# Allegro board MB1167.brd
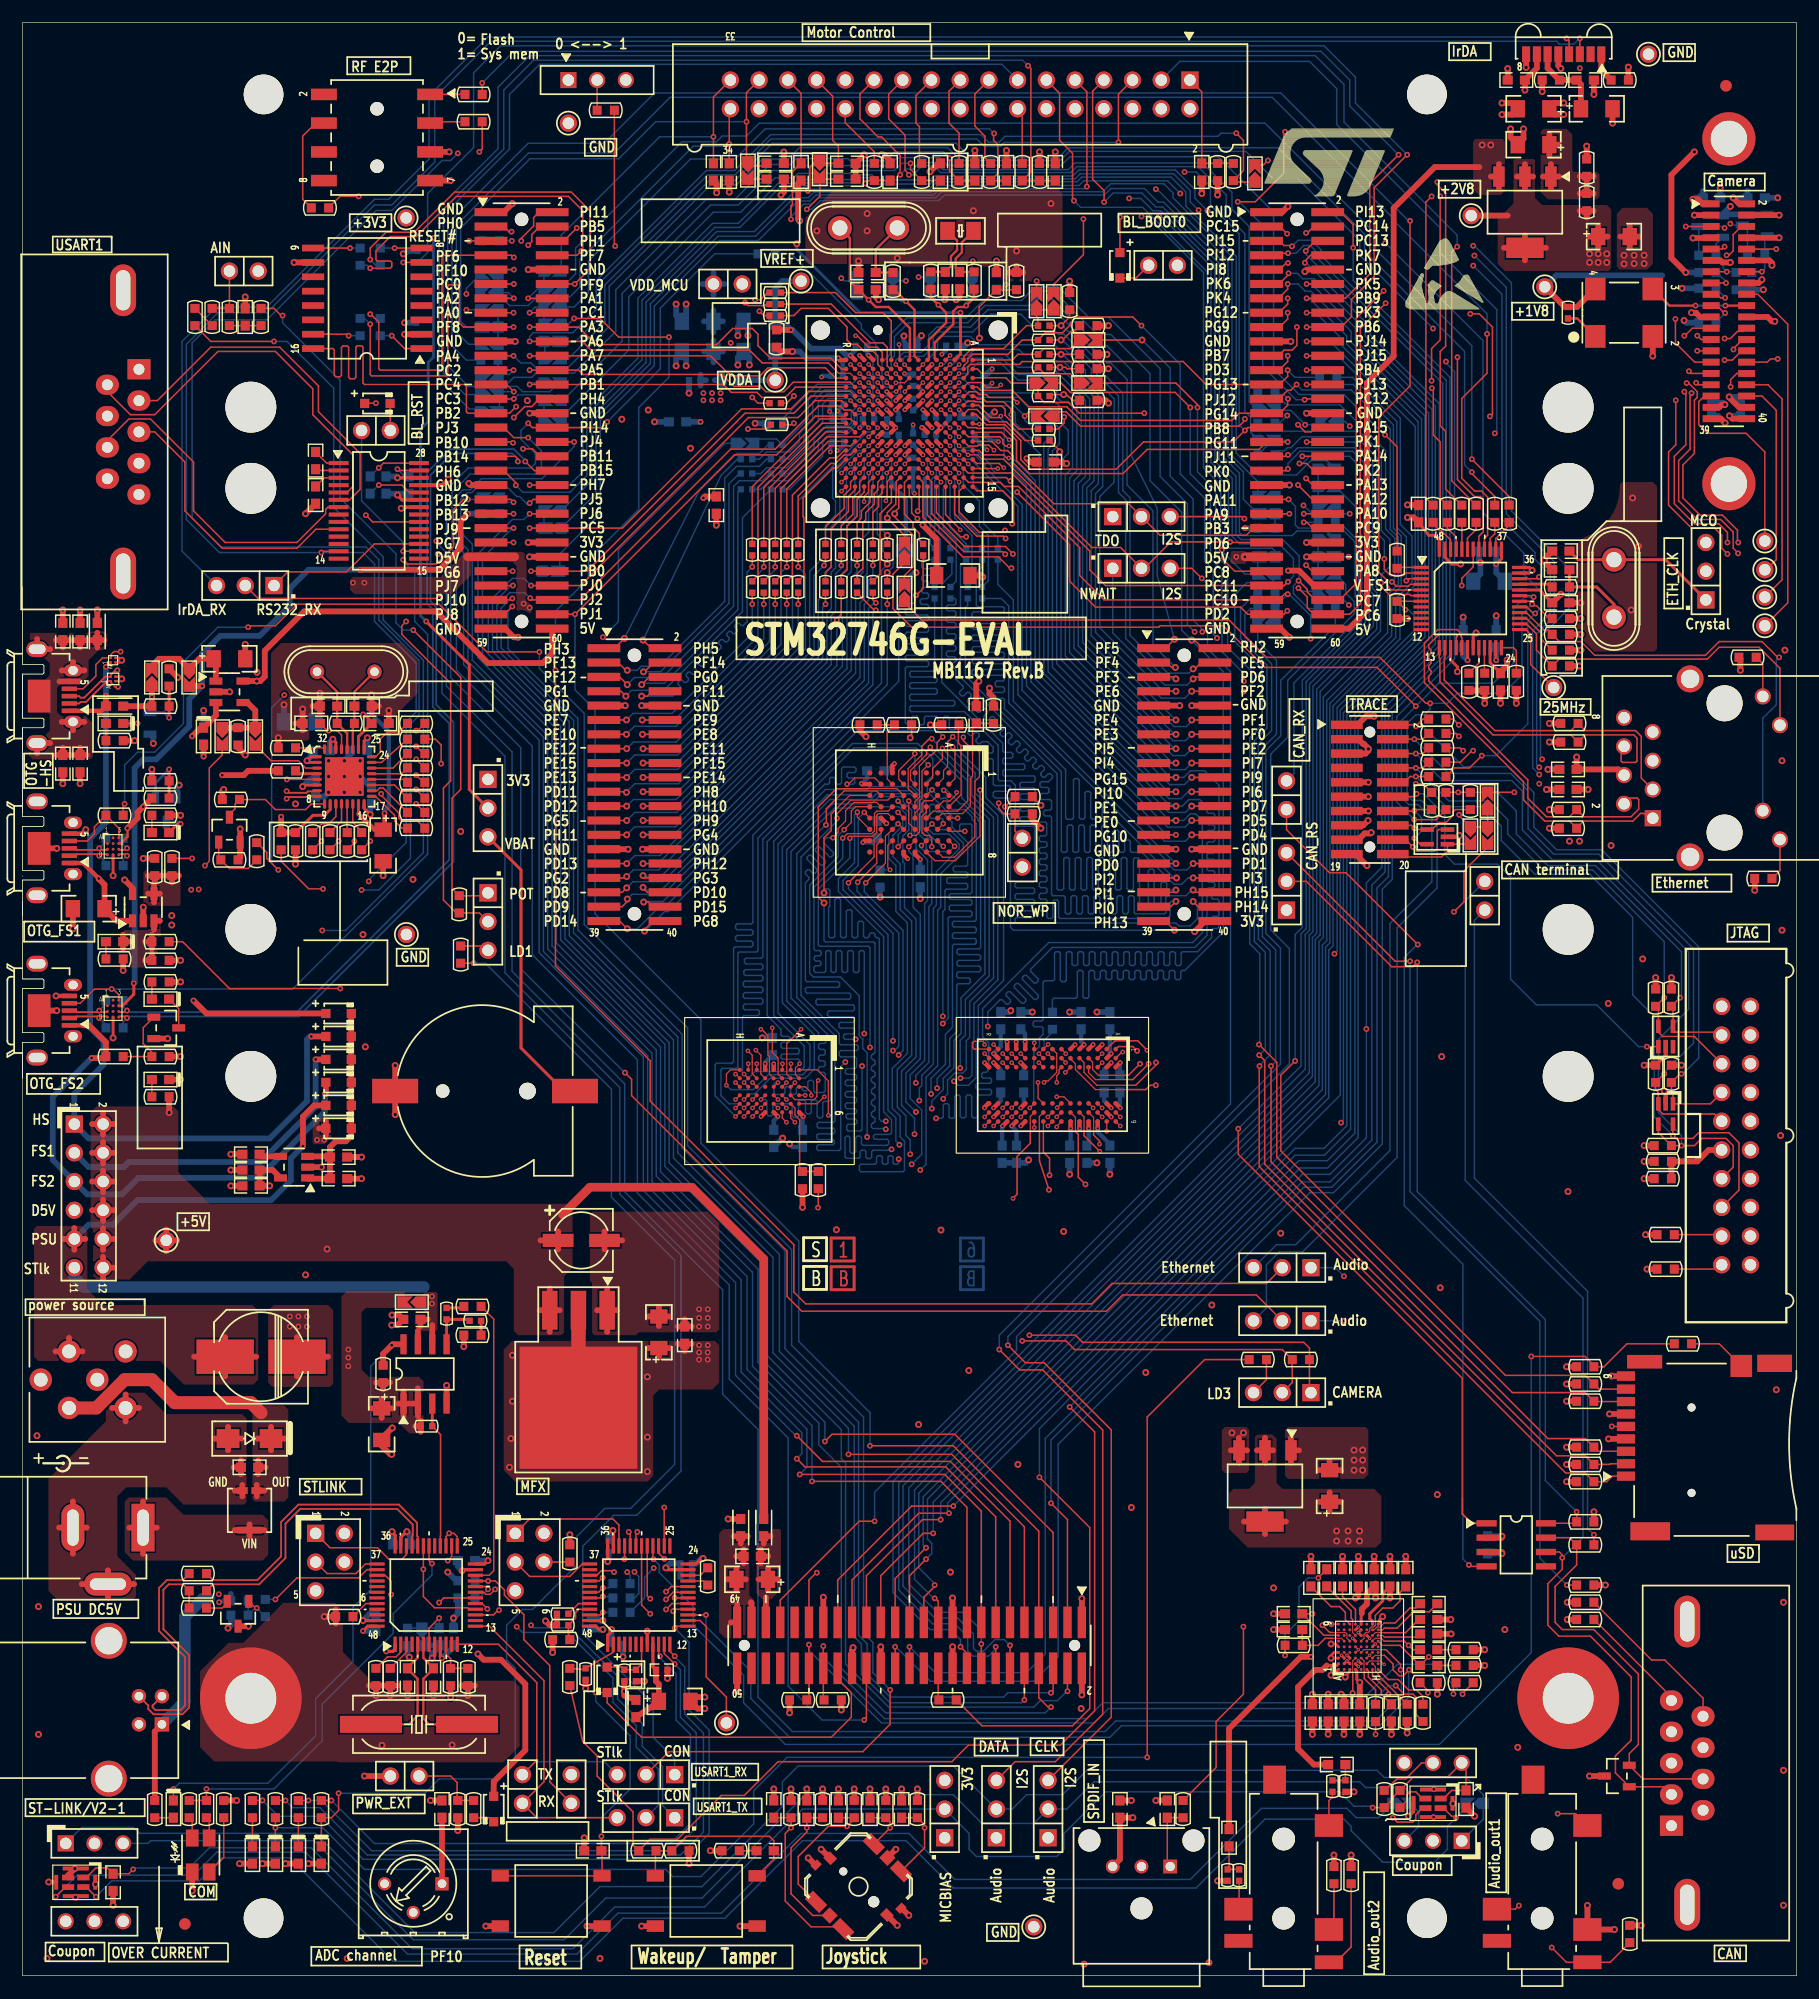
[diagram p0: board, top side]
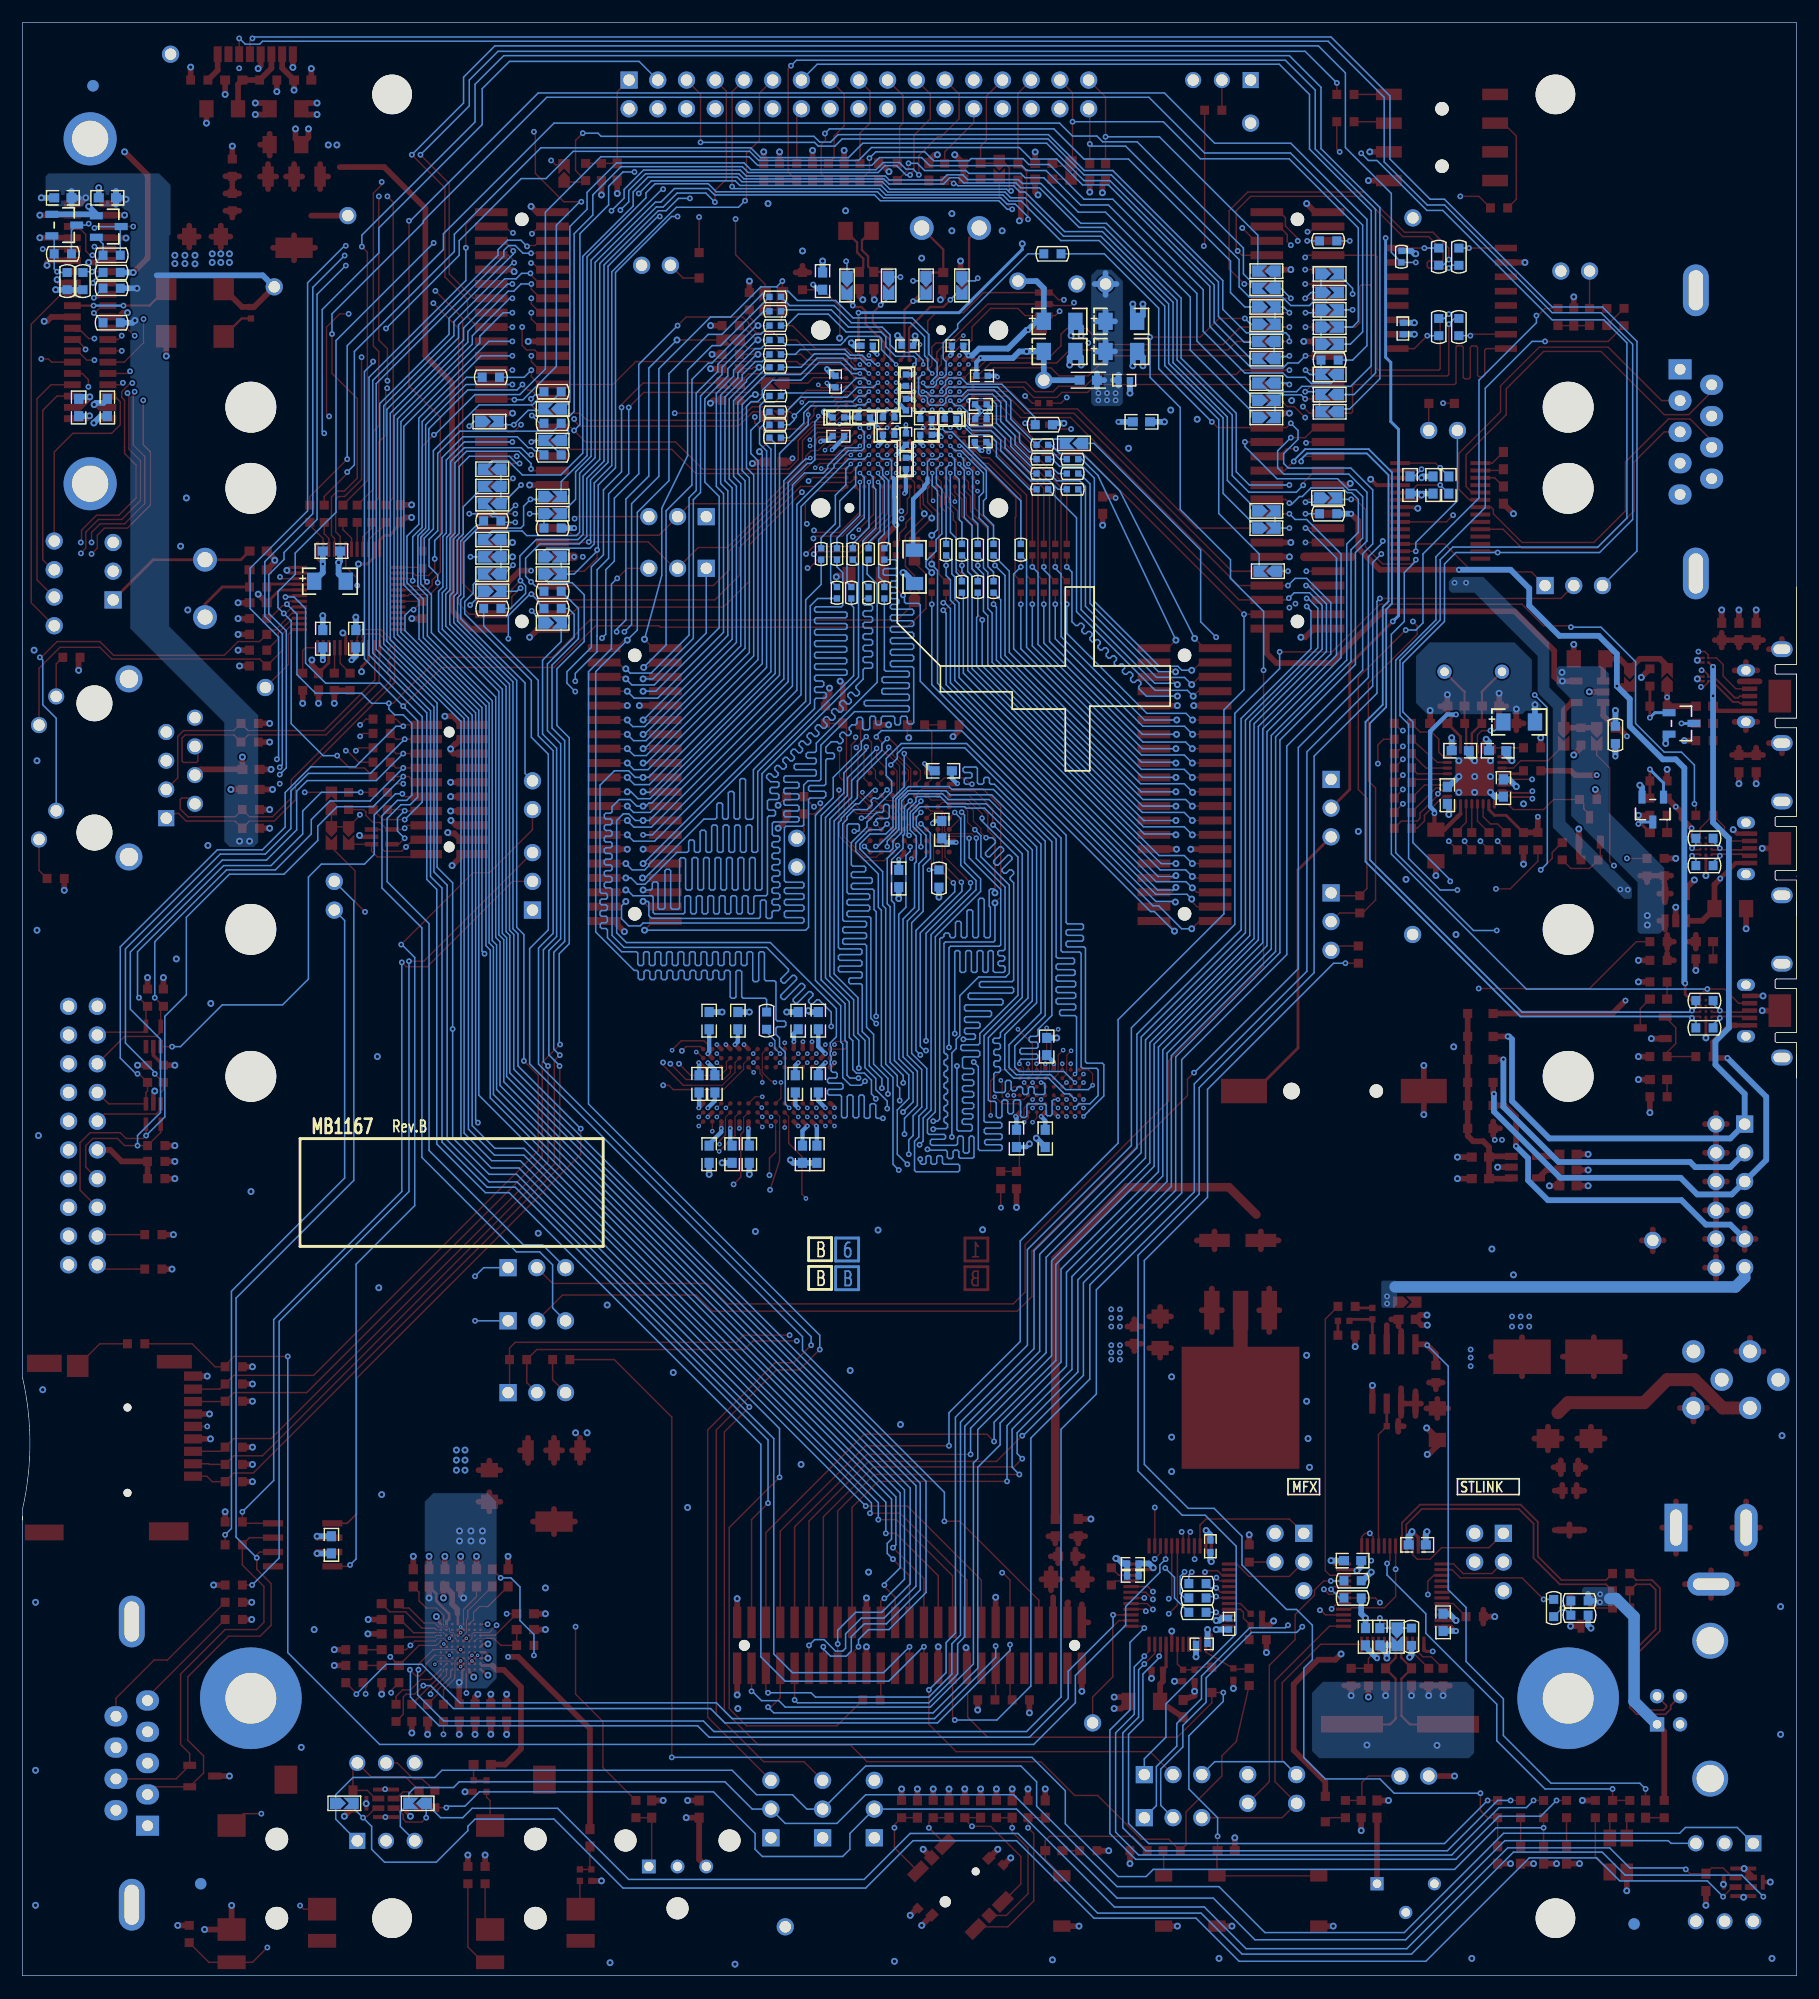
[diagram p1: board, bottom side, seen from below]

Outline 156.84 x 172.72 mm; copper layers: TOP, L2_GND, L3_VCC, L4_SIG, L5_GND, BOTTOM. Coordinates in mm from the lower left corner of the outline.
Outline path: 0,115.14 0,111.25 ; 0,110.36 0,102.87 ; 0,97.26 0,97.21 ; 0,172.72 156.84,172.72 156.84,52.86 arc(156.2,47.08) 156.84,41.3 156.84,40.28 156.84,40.59 156.84,0 0,0 0,81.53 0,79.38 0,82.54 1.79,82.54 1.89,82.64 1.89,83.29 1.79,83.39 0,83.39 0,87.29 1.79,87.29 1.89,87.39 1.89,88.04 1.79,88.14 0,88.14 0,95 0,93.73 0,96.89 1.79,96.89 1.89,96.99 1.89,97.64 1.79,97.75 0,97.75 0,101.64 1.79,101.64 1.89,101.75 1.89,102.4 1.79,102.5 0,102.5 0,109.35 0,107.19 0,110.36 1.79,110.36 1.89,110.46 1.89,111.11 1.79,111.21 0,111.21 0,115.11 1.79,115.11 1.89,115.21 1.89,115.86 1.79,115.96 0,115.96 0,172.72

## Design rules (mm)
net group A0: nets A0 NETR242_1
net group A1: nets A1 NETR240_1
net group A2: nets A2 NETR239_1
net group A3: nets A3 NETR236_1
net group A4: nets A4 NETR233_1
net group A5: nets A5 NETR232_1
net group A6: nets A6 NETR255_1
net group A7: nets A7 NETR253_1
net group A8: nets A8 NETR256_1
net group A9: nets A9 NETR266_1
net group A10: nets A10 NETR258_1
net group A11: nets A11 NETR257_1
net group A12: nets A12 NETR272_1
net group A13: nets A13 NETR262_1
net group A14: nets A14 NETR273_1
net group A15: nets A15 NETR264_1
net group A16: nets A16 NETR265_2
net group A17: nets A17 NETR274_1
net group A18: nets A18 NETR263_1
net group A19: nets A19 NETR37_1
net group A20: nets A20 NETR35_1
net group A21: nets A21 NETR31_1
net group A22: nets A22 NETR34_1
net group BOOT0: nets BOOT0 NETR4_2
net group D0: nets D0 NETR72_1
net group D1: nets D1 NETR60_1
net group D2: nets D2 NETR267_1
net group D3: nets D3 NETR276_1
net group D4: nets D4 NETR63_1
net group D5: nets D5 NETR53_1
net group D6: nets D6 NETR52_1
net group D7: nets D7 NETR64_1
net group D8: nets D8 NETR54_1
net group D9: nets D9 NETR65_1
net group D10: nets D10 NETR67_1
net group D11: nets D11 NETR55_1
net group D12: nets D12 NETR66_1
net group D13: nets D13 NETR59_1
net group D14: nets D14 NETR70_1
net group D15: nets D15 NETR71_1
net group D16: nets D16 NETR56_2
net group D17: nets D17 NETR57_2
net group D18: nets D18 NETR68_2
net group D19: nets D19 NETR69_2
net group D20: nets D20 NETR58_2
net group D21: nets D21 NETR271_2
net group D22: nets D22 NETR279_2
net group D23: nets D23 NETR278_2
net group D24: nets D24 NETR270_2
net group D25: nets D25 NETR269_2
net group D26: nets D26 NETR268_2
net group D27: nets D27 NETR277_2
net group D28: nets D28 NETR250_2
net group D29: nets D29 NETR245_2
net group D30: nets D30 NETR246_2
net group D31: nets D31 NETR248_2
net group DIFFPAIR1: nets NETCN9_2 NETCN9_3
net group NETC11_1: nets NETC11_1 NETCN1_26
net group NETC12_2: nets NETC12_2 NETCN1_19
net group NETC13_2: nets NETC13_2 NETCN1_17
net group NETC14_2: nets NETC14_2 NETCN1_15
net group NETC15_1: nets NETC15_1 NETCN1_14
net group NETC16_2: nets NETC16_2 PA6
net group NETC20_1: nets NETC20_1 PH0
net group NETC21_1: nets NETC21_1 PC15
net group NETC22_1: nets NETC22_1 PC14
net group NETC25_1: nets NETC25_1 NETC25_2
net group NETC31_2: nets NETC31_2 NETR73_1
net group NETC38_1: nets NETC38_1 NETC39_1
net group NETC71_1: nets NETC71_1 NETC71_2
net group NETC76_1: nets NETC76_1 NETC76_2
net group NETC77_1: nets NETC77_1 NETC77_2
net group NETC97_1: nets NETC97_1 PG12
net group NETC136_1: nets NETC136_1 NETC136_2
net group NETCN12_2: nets NETCN12_2 PA13
net group NETCN12_4: nets NETCN12_4 PA14
net group NETCN12_8: nets NETCN12_8 PA15
net group NETCN13_2: nets NETCN13_2 PA11
net group NETCN13_3: nets NETCN13_3 NETD5_C3
net group NETCN13_4: nets NETCN13_4 PA10
net group NETCN14_3: nets NETCN14_3 PB15
net group NETCN16_2: nets NETCN16_2 PAR_D4
net group NETCN16_8: nets NETCN16_8 PAR_D3
net group NETCN16_10: nets NETCN16_10 NETR154_1
net group NETCN20_22: nets NETCN20_22 PK7
net group NETCN21_2: nets NETCN21_2 STL_USB_DM
net group NETCN22_7: nets NETCN22_7 NETJP12_1
net group NETD15_2: nets NETD15_2 NETJP15_2
net group NETJP19_3: nets NETJP19_3 PAR_D1
net group NETLD1_2: nets NETLD1_2 NETR207_1
net group NETLD2_2: nets NETLD2_2 NETR206_1
net group NETLD3_2: nets NETLD3_2 NETR205_1
net group NETLD4_2: nets NETLD4_2 NETR204_1
net group NETLD6_2: nets NETLD6_2 NETR121_1
net group NETR42_1: nets NETR42_1 PB2
net group NETR43_1: nets NETR43_1 PB6
net group NETR44_1: nets NETR44_1 PG15
net group NETR45_1: nets NETR45_1 PH7
net group NETR46_1: nets NETR46_1 NETR46_2
net group NETR47_1: nets NETR47_1 NETR47_2
net group NETR48_1: nets NETR48_1 NETR48_2
net group NETR49_1: nets NETR49_1 NETR49_2
net group NETR50_1: nets NETR50_1 NETR50_2
net group NETR51_1: nets NETR51_1 PF11
net group NETR61_1: nets NETR61_1 PG8
net group NETR62_1: nets NETR62_1 NETR62_2
net group NETR88_1: nets NETR88_1 PA3
net group NETR90_1: nets NETR90_1 PD7
net group NETR95_1: nets NETR95_1 PB0
net group NETR100_1: nets NETR100_1 PB1
net group NETR102_1: nets NETR102_1 PB10
net group NETR106_1: nets NETR106_1 PB11
net group NETR107_1: nets NETR107_1 PD5
net group NETR109_1: nets NETR109_1 PB12
net group NETR119_1: nets NETR119_1 PB5
net group NETR123_1: nets NETR123_1 PH4
net group NETR124_1: nets NETR124_1 PI11
net group NETR125_1: nets NETR125_1 PC0
net group NETR126_1: nets NETR126_1 PA5
net group NETR146_1: nets NETR146_1 PG10
net group NETR193_1: nets NETR193_1 PG9
net group NETR225_2: nets NETR225_2 PI14
net group NETR241_2: nets NETR241_2 PC2
net group NETR243_2: nets NETR243_2 PG13
net group NETR244_2: nets NETR244_2 PG14
net group NETR251_2: nets NETR251_2 PH3
net group NETR252_2: nets NETR252_2 PG11
net group NETR254_2: nets NETR254_2 PH5
net group NETR287_1: nets NETR287_1 PH2
net group NETR295_2: nets NETR295_2 PI8
net group VDDA: nets VDDA VREF+
net group +1V8: nets NETR25_1
net group +2V8: nets I2C1_SCL_C I2C1_SDA_C NETCN2_3 NETR195_2 NETR290_2 PB8
net group +3V3_ST_LINK: nets +3V3_ST_LINK NETLD12_4 STM_RST
net group +5V: nets NETLD10_1
net group A23: nets A23 NETR39_1 NETR247_1
net group ADDRESS: nets NETR285_1
net group CUR_SEL: nets CUR_SEL NETR150_2 NETR151_2 NETR152_1
net group DATA: nets PE0 PE1 PI4 PI5
net group LED_STLINK: nets LED_STLINK NETLD12_2 NETLD12_3
net group MIC_VDD: nets MIC_VDD NETCN24_5 NETR199_1
net group NETB2_2: nets NETB2_2 NETR180_1 PC13
net group NETC24_2: nets NETC24_2 NETCN3_1 NETJP24_1 NETR27_1 NETR27_2
net group NETC64_1: nets NETC64_1 NETC64_2 NETC74_2
net group NETC88_1: nets NETC88_1 NETC88_2 NETCN25_6
net group NETC98_1: nets NETC98_1 NETC98_2 NETCN25_4
net group NETCN2_1: nets NETCN2_1 NETR189_2 NETR291_2 PB9
net group NETCN12_10: nets NETCN5_5 NETCN12_10 NETR127_1 RESET#
net group NETCN12_14: nets NETCN12_6 NETCN12_14 T_JTDO
net group NETCN12_16: nets NETCN12_16 NETCN15_3 PB4
net group NETCN14_2: nets NETCN14_2
net group NETCN16_1: nets NETCN2_4 NETCN16_1 PAR_D8
net group NETCN21_3: nets NETCN21_3 NETR171_2 STL_USB_DP
net group NETL2_1: nets NETL2_1 NETR80_2 NETR103_1
net group NETLD8_2: nets NETR132_1
net group NETLD11_2: nets NETLD11_2 NETR293_1 PWR_ENN USB_RENUMN VUSB_ST_LINK
net group NETR105_2: nets NETR105_2 PA9 VBUS_FS1
net group NETR115_1: nets NETR115_1 NETR138_2 PB13 VBUS_FS2
net group NETR129_2: nets NETR130_2
net group NETR227_1: nets NETR26_1 NETR227_1 PF9
net group NETR228_2: nets NETR22_1 NETR228_2 PF7
net group NETR237_1: nets NETR24_1 NETR237_1 PF6
net group NETR238_2: nets NETR41_1 NETR238_2 PF8

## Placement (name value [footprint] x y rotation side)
B1  TD-0341 [RESET_Black]  [PB10]  46.74 6.6 0 top
B2  WKUP_TAMPER  [PB10]  60.45 6.6 0 top
B3  EVQQ7  [SW-JOY]  73.91 7.87 45 top
BT1  CR1220 holder  [BAT_2SM_CR1220]  40.89 78.23 180 top
C1  100nF  [0603C]  132.08 167.64 180 top
C2  100nF  [0603C]  138.18 167.64 0 top
C3  4.7uF  [TAN-A]  133.6 165.1 0 top
C4  4.7uF  [TAN-A]  139.19 165.1 180 top
C5  10uF  [TAN-A]  133.6 161.93 0 top
C6  [N_A]  [0603C]  66.55 160.27 180 top
C7  [N_A]  [0603C]  72.9 160.27 180 top
C8  [N_A]  [0603C]  61.09 159.51 90 top
C9  [N_A]  [0603C]  62.48 159.51 90 top
C10  [N_A]  [0603C]  68.83 159.51 90 top
C11  100nF  [0603C]  76.71 159.51 90 top
C12  [N_A]  [0603C]  81.15 159.51 270 top
C13  [N_A]  [0603C]  84.2 159.51 270 top
C14  [N_A]  [0603C]  87 159.51 270 top
C15  100nF  [0603C]  91.31 159.51 90 top
C16  1nF  [0603C]  104.27 159.51 90 top
C17  10nF  [0603C]  66.55 158.88 0 top
C18  [N_A]  [0603C]  72.9 158.88 180 top
C19  10uF  [TAN-A]  140.72 153.8 180 top
C20  20pF  [0603C]  74.68 150.62 180 top
C21  1.5pF  [0603C]  81.58 149.91 270 top
C22  1.5pF  [0603C]  82.85 149.91 270 top
C23  20pF  [0603C]  74.68 149.1 0 top
C24  [N_A]  [0603C]  19.68 146.69 270 top
C25  100nF  [0603C]  25.91 133.99 270 top
C26  [N_A]  [0603C]  90.42 133.86 180 top
C27  100nF  [0603C]  25.91 130.94 90 top
C28  [N_A]  [0603C]  61.34 130.05 90 top
C29  100nF  [0603C]  123.44 129.29 90 top
C30  22pF  [0603C]  136.02 125.98 180 top
C31  22pF  [0603C]  136.02 124.33 0 top
C32  2.2uF  [1206C]  82.3 123.83 0 top
C33  100nF  [0603C]  136.02 121.41 180 top
C34  100nF  [0603C]  3.56 118.87 90 top
C35  100nF  [0603C]  5.08 118.87 90 top
C36  4.7uF  [TAN-A]  18.29 116.46 180 top
C37  100nF  [0603C]  130.68 114.43 90 top
C38  33pF  [0603C]  27.05 112.27 180 top
C39  33pF  [0603C]  30.1 112.27 0 top
C40  100nF  [0603C]  84.33 111.51 90 top
C41  100nF  [0603C]  25.53 110.74 180 top
C42  100nF  [0603C]  31.62 110.74 0 top
C43  100nF  [0603C]  3.56 107.19 270 top
C44  100nF  [0603C]  5.08 107.19 270 top
C45  100nF  [0603C]  136.65 106.68 0 top
C46  100nF  [0603C]  136.65 104.9 0 top
C47  4.7uF  [TAN-A]  31.88 99.95 90 top
C48  4.7uF  [TAN-A]  5.84 94.36 0 top
C49  10nF_X7R_0603  [0603C]  20.19 72.64 0 top
C50  1uF_X5R_0603  [0603C]  27.94 72.39 180 top
C51  100nF  [0603C]  20.19 71.25 0 top
C52  100nF  [0603C]  27.94 70.48 180 top
C53  1uF_X5R_0603  [0603C]  20.19 69.85 180 top
C54  47uF  [CAE_5R3X5R3_H5R4]  49.4 65.02 0 top
C55  100nF  [0603C]  34.42 58.04 0 top
C56  10uF  [TAN-A]  56.26 56.9 270 top
C57  100nF  [0603C]  58.55 56.64 90 top
C58  220uF  [C310M-6]  21.08 54.74 180 top
C59  4.7uF  [TAN-A]  31.75 48.77 90 top
C60  100nF  [0603C]  20.07 44.96 180 top
C61  10uF  [TAN-A]  115.57 43.31 270 top
C62  100nF  [0603C]  64.52 37.08 180 top
C63  4.7uF  [0603C]  113.92 35.18 270 top
C64  1uF  [0603C]  115.32 35.18 90 top
C65  4.7uF  [0603C]  116.71 35.18 90 top
C66  4.7uF  [0603C]  118.11 35.18 90 top
C67  1uF  [0603C]  119.51 35.18 90 top
C68  100nF  [0603C]  120.9 35.18 90 top
C69  1uF  [0603C]  122.3 35.18 90 top
C70  10uF  [TAN-A]  64.52 35.05 0 top
C71  2.2uF  [0603C]  124.33 32.89 180 top
C72  4.7uF  [0603C]  112.39 32 0 top
C73  2.2uF  [0603C]  124.33 31.5 0 top
C74  4.7uF  [0603C]  112.39 30.61 0 top
C75  2.2uF  [0603C]  124.33 30.23 0 top
C76  100nF  [0603C]  124.33 28.83 0 top
C77  100nF  [0603C]  124.33 27.43 0 top
C78  100nF  [0402C]  56.52 27.05 180 top
C79  100nF[N_A]  [0402C]  54.23 26.54 90 top
C80  20pF  [0603C]  34.04 26.42 270 top
C81  20pF  [0603C]  36.32 26.42 270 top
C82  1uF  [TAN-A]  57.66 24.26 180 top
C83  100nF  [0603C]  114.05 23.24 270 top
C84  100nF  [0603C]  115.44 23.24 270 top
C85  4.7uF  [0603C]  116.84 23.24 270 top
C86  100nF  [0603C]  118.24 23.24 270 top
C87  1uF  [0603C]  121.03 23.24 270 top
C88  4.7uF  [0603C]  116.2 18.67 180 top
C89  100nF  [0603C]  127.64 15.62 270 top
C90  100nF  [0603C]  37.08 14.73 90 top
C91  10nF[N_A]  [0603C]  66.42 14.73 270 top
C92  10nF[N_A]  [0603C]  69.34 14.73 270 top
C93  10nF[N_A]  [0603C]  72.14 14.73 270 top
C94  10nF[N_A]  [0603C]  74.93 14.73 270 top
C95  10nF[N_A]  [0603C]  77.72 14.73 270 top
C96  100nF  [0603C]  97.03 14.73 270 top
C97  30pF  [0603C]  101.22 14.73 90 top
C98  4.7uF  [0603C]  106.68 12.19 90 top
C99  100nF  [0603C]  50.42 11.05 0 top
C100  [N_A]  [0603C]  65.66 11.05 0 top
C101  100nF  [0603C]  8 8.26 270 top
C102  100nF  [0603C]  153.29 157.23 0 bottom
C103  100nF  [0603C]  149.35 157.23 180 bottom
C104  [N_A]  [0603C]  86.11 149.86 270 bottom
C105  1uF  [TAN-A]  65.15 146.3 0 bottom
C106  4.7uF  [TAN-A]  59.69 146.3 0 bottom
C107  100nF  [0402C]  34.8 145.67 90 bottom
C108  100nF  [0402C]  82.17 144.15 0 bottom
C109  100nF  [0402C]  78.61 144.15 0 bottom
C110  100nF  [0402C]  74.17 144.15 180 bottom
C111  1uF  [TAN-A]  65.15 143.64 0 bottom
C112  4.7uF  [TAN-A]  59.69 143.64 0 bottom
C113  100nF  [0402C]  72.01 141.48 0 bottom
C114  100nF  [0402C]  78.74 141.1 90 bottom
C115  100nF  [0402C]  59.44 141.1 180 bottom
C116  100nF  [0402C]  84.96 140.97 90 bottom
C117  100nF  [0402C]  72.11 138.96 180 bottom
C118  100nF  [0402C]  78.74 138.94 270 bottom
C119  100nF  [0603C]  151.89 138.68 90 bottom
C120  100nF  [0603C]  149.35 138.68 90 bottom
C121  100nF  [0402C]  84.71 137.79 180 bottom
C122  100nF  [0402C]  82.42 137.79 0 bottom
C123  100nF  [0402C]  80.26 137.79 180 bottom
C124  100nF  [0402C]  76.96 137.67 0 bottom
C125  100nF  [0402C]  74.8 137.67 180 bottom
C126  100nF  [0402C]  72.11 137.64 180 bottom
C127  [N_A]  [0603C]  57.91 137.41 0 bottom
C128  100nF  [0402C]  80.26 136.27 180 bottom
C129  100nF  [0402C]  76.96 136.27 0 bottom
C130  100nF  [0402C]  84.71 136.14 180 bottom
C131  100nF  [0402C]  78.74 135.89 90 bottom
C132  100nF  [0402C]  72.14 135.64 180 bottom
C133  100nF  [0402C]  78.74 133.73 270 bottom
C134  100nF  [0603C]  34.16 131.83 90 bottom
C135  100nF  [0603C]  32.13 131.83 270 bottom
C136  100nF  [0603C]  30.73 131.83 90 bottom
C137  100nF  [0603C]  129.54 125.98 0 bottom
C138  2.2uF  [1206C]  77.98 124.59 270 bottom
C139  10uF  [TAN-A]  129.67 123.32 0 bottom
C140  100nF  [0603C]  130.3 118.24 90 bottom
C141  100nF  [0603C]  127.38 118.24 270 bottom
C142  4.7uF  [TAN-A]  24.51 110.87 0 bottom
C143  100nF  [0603C]  29.72 108.33 180 bottom
C144  100nF  [0603C]  26.42 108.33 180 bottom
C145  100nF  [0603C]  75.44 106.55 180 bottom
C146  100nF  [0603C]  25.91 105.03 270 bottom
C147  100nF  [0603C]  30.86 104.39 90 bottom
C148  100nF  [0603C]  75.56 101.35 270 bottom
C149  100nF  [0603C]  79.38 97.03 270 bottom
C150  100nF  [0603C]  96.14 84.45 90 bottom
C151  100nF  [0603C]  93.6 84.45 90 bottom
C152  100nF  [0603C]  88.27 84.45 90 bottom
C153  100nF  [0603C]  86.49 84.45 90 bottom
C154  100nF  [0603C]  66.29 82.17 90 bottom
C155  100nF  [0603C]  97.03 78.87 90 bottom
C156  100nF  [0603C]  95.63 78.87 90 bottom
C157  100nF  [0603C]  88.52 78.87 90 bottom
C158  100nF  [0603C]  86.49 78.87 90 bottom
C159  100nF  [0603C]  68.96 74.04 270 bottom
C160  100nF  [0603C]  66.42 74.04 270 bottom
C161  100nF  [0603C]  96.14 72.64 270 bottom
C162  100nF  [0603C]  94.11 72.64 270 bottom
C163  100nF  [0603C]  92.58 72.64 270 bottom
C164  100nF  [0603C]  87.88 72.64 270 bottom
C165  100nF  [0603C]  86.61 72.64 270 bottom
C166  100nF  [0603C]  129.54 38.1 90 bottom
C167  100nF  [0603C]  33.53 38.1 180 bottom
C168  100nF  [0402C]  51.82 37.97 270 bottom
C169  100nF  [0603C]  39.24 36.7 0 bottom
C170  100nF  [0402C]  58.67 36.45 180 bottom
C171  100nF  [0402C]  58.67 35.31 0 bottom
C172  100nF  [0603C]  31.24 31.24 270 bottom
C173  100nF  [0402C]  50.16 31.11 270 bottom
C174  100nF  [0603C]  38.1 29.97 270 bottom
C175  100nF  [0603C]  36.83 29.97 90 bottom
C176  100nF  [0402C]  52.58 29.34 180 bottom
CN1  MC_connector  [IDC34S]  103.22 167.64 270 top
CN2  F206A-2_04MGF-A  [SSM-104-L-DH]  31.34 162.56 90 top
CN3  -  [SIP2]  18.29 150.75 0 top
CN4  F1000-2_20MGF-L0A  [CLM-120-02-L-D]  150.88 147.19 270 top
CN5  P1039-2_30MGF-089-1A  [FTR-130-53-L-D-LC]  44.12 137.54 270 top
CN6  P1039-2_30MGF-089-1A  [FTR-130-53-L-D-LC]  112.7 137.54 270 top
CN7  DB9-male USART1  [DB9_M]  10.29 136.53 90 top
CN8  475900001  [MOLEX_47590001]  4.14 113.16 270 top
CN9  J0011D21B  [RJ45_J0011D01BNL]  144.15 102.36 270 top
CN10  P1039-2_20MGF-089-1A  [FTR-120-53-L-D-LC]  54.1 105.33 270 top
CN11  P1039-2_20MGF-089-1A  [FTR-120-53-L-D-LC]  102.72 105.33 270 top
CN12  P127B-2_10MGF-079-1E7A  [FTSH-110-01-L-DV]  119.13 104.9 270 top
CN13  475900001  [MOLEX_47590001]  4.14 99.69 270 top
CN14  475900001  [MOLEX_47590001]  4.14 85.34 270 top
CN15  JTAG  [IDC20S]  150.24 85.72 0 top
CN16  PJS008-2000  [MSD_PJS008_]  147.57 42.7 90 top
CN17  DC-10B  [PWR_JACK_DC10]  10.64 39.62 0 top
CN18  [N_A]  [HDR_2X3-1_2R54-6]  25.91 39.12 270 top
CN19  [N_A]  [HDR_2X3-1_2R54-6]  43.56 39.12 270 top
CN20  P127B-2_25MGF-079-1A  [FTSH-125-01-F-DV]  78.42 29.21 180 top
CN21  USB-typeB connector  [USB-B]  12.32 22.23 270 top
CN22  DB9-male CAN connector  [DB9_M]  145.8 18.8 270 top
CN23  -  [SIP2]  44.2 15.24 90 top
CN24  Coupon Connectors  [COUPON]  124.71 15.37 90 top
CN25  PJ3028B-3  [PJ3028B]  111.51 5.08 90 top
CN26  PJ3028B-3  [PJ3028B]  134.37 5.08 90 top
CN27  Coupon Connectors  [COUPON]  6.35 8.26 270 top
CN28  DLR11H0  [CONN_DLR11H0]  101.47 9.65 0 top
D1  BAT60JFILM  [SOD-323]  97.03 151.26 270 top
D2  BAT60JFILM  [SOD-323]  31.37 139.04 0 top
D3  ESDA14V2-2BF3  [BGA4_0R4_0R8X0R8]  8 116.33 90 top
D4  USBULC6-2F3  [BGA4_0R4_1X1]  8 114.68 90 top
D5  EMIF02-USB03F2  [BGA11_0R5_1R57X2R07]  8 99.87 0 top
D6  EMIF02-USB03F2  [BGA11_0R5_1R57X2R07]  8 85.52 0 top
D7  BAT60JFILM  [SOD-323]  27.94 85.09 0 top
D8  BAT60JFILM  [SOD-323]  27.94 83.06 0 top
D9  BAT60JFILM  [SOD-323]  27.94 81.03 0 top
D10  BAT60JFILM  [SOD-323]  27.94 78.99 0 top
D11  BAT60JFILM  [SOD-323]  27.94 76.96 0 top
D12  BAT60JFILM  [SOD-323]  27.94 74.93 0 top
D13  ZEN056V130A24LS  [TYCO_ZEN056V130A24LS]  20.07 41.15 90 top
D14  ESDCAN24-2BLY  [SOT-23]  140.97 17.65 90 top
D15  BAT60JFILM  [SOD-323]  41.66 14.73 270 top
D16  BAT60JFILM  [SOD-323]  51.69 26.16 270 top
H1  POSITION HOLE  [HOLE_C9D4R5]  20.18 24.53 0 top
H2  POSITION HOLE  [HOLE_C9D4R5]  136.66 24.53 0 top
JP1  -  [SIP2]  99.57 151.26 0 top
JP2  -  [SIP2]  63.63 149.61 180 top
JP3  -  [SIP2]  32.51 136.65 180 top
JP4  -  [SIP3]  96.39 129.03 0 top
JP5  -  [SIP3]  96.39 124.46 0 top
JP6  -  [SIP3]  148.84 121.67 90 top
JP7  -  [SIP3]  22.23 122.94 180 top
JP8  -  [SIP2]  111.76 105.66 270 top
JP9  -  [SIP3]  41.15 105.79 270 top
JP10  -  [SIP2]  88.39 98.04 90 top
JP11  -  [SIP3]  111.76 94.23 90 top
JP12  -  [SIP2]  129.29 94.23 90 top
JP13  Header 6X2  [HDR_2X6_2R54]  4.57 75.31 270 top
JP14  -  [SIP3]  57.66 17.78 180 top
JP15  -  [SIP2]  32.51 17.65 0 top
JP16  [N_A]  [SIP2]  48.51 17.78 270 top
JP17  -  [SIP3]  81.53 12.19 90 top
JP18  -  [SIP3]  86.11 12.19 90 top
JP19  -  [SIP3]  90.68 12.19 90 top
JP20  -  [SIP3]  57.66 13.97 180 top
JP21  -  [SIP3]  113.92 57.91 180 top
JP22  -  [SIP3]  113.92 62.61 180 top
JP23  -  [SIP3]  113.92 51.56 180 top
JP24  -  [SIP3]  41.15 95.76 270 top
L1  EXC-3BP121H[BEAD]  [0603L]  6.6 118.87 270 top
L2  EXC-3BP121H[BEAD]  [0603L]  8.13 112.27 180 top
L3  BNX002-01  [BNX001]  6.6 52.7 180 top
L4  BEAD(FCM1608KF-601T03)  [0603L]  63.5 39.62 270 top
L5  BEAD(FCM1608KF-601T03)  [0603L]  65.53 39.62 270 top
L6  Ferrite  [0603L]  54.23 23.62 270 top
L7  BEAD(FCM1608KF-601T03)  [0603L]  62.61 141.1 0 bottom
LD1  Green  [0603D]  26.42 10.67 90 top
LD2  Orange  [0603D]  24.38 10.67 90 top
LD3  Red  [0603D]  22.35 10.67 90 top
LD4  Blue  [0603D]  20.32 10.67 90 top
LD5  Green  [0603D]  8.13 110.74 0 top
LD6  Red  [0603D]  16 109.6 90 top
LD7  Green  [0603D]  12.19 101.09 0 top
LD8  Red  [0603D]  8.13 91.44 0 top
LD9  Green  [0603D]  12.19 86.36 0 top
LD10  red  [0603D]  12.19 79.25 0 top
LD11  Red  [0603D]  13.34 14.73 90 top
LD12  HSMF-A201-A00J1  [LED2_3528]  15.75 10.67 0 top
NOREF  -  [unnamed]  20.18 131.53 0 top
NOREF#2  -  [#2]  12.32 228.5 0 top
NOREF#3  -  [unnamed]  21.31 5.08 0 top
NOREF#4  -  [unnamed]  14.35 4.57 0 top
NOREF#5  -  [unnamed]  20.18 79.53 0 top
NOREF#6  -  [#2]  0 0 0 top
NOREF#7  -  [#2]  322.2 176.15 0 top
NOREF#8  -  [#2]  450.6 -120.4 0 top
NOREF#9  -  [unnamed]  136.66 131.53 0 top
NOREF#10  -  [unnamed]  20.18 92.53 0 top
NOREF#11  -  [#2]  72.26 60.92 0 top
NOREF#12  -  [unnamed]  21.31 166.37 0 top
NOREF#13  -  [#2]  72.26 63.46 0 top
NOREF#14  -  [unnamed]  136.66 138.71 0 top
NOREF#15  -  [unnamed]  124.18 5.08 0 top
NOREF#16  -  [#2]  283.34 118.87 0 top
NOREF#17  -  [#2]  13.59 -41.66 0 top
NOREF#18  -  [unnamed]  124.18 166.37 0 top
NOREF#19  -  [unnamed]  136.66 92.53 0 top
NOREF#20  -  [unnamed]  141.1 8.13 0 top
NOREF#21  -  [unnamed]  136.66 79.53 0 top
NOREF#22  -  [unnamed]  20.18 138.71 0 top
NOREF#23  -  [unnamed]  150.62 167.13 0 top
NOREF#24  -  [unnamed]  141.1 8.13 180 bottom
NOREF#25  -  [unnamed]  150.62 167.13 180 bottom
NOREF#26  -  [unnamed]  14.35 4.57 180 bottom
R1  47  [0603R]  135.13 167.64 0 top
R2  5.1  [0603R]  141.22 167.64 180 top
R3  0  [0603R]  39.88 166.37 180 top
R4  10K  [0603R]  51.56 164.97 180 top
R5  0  [0603R]  39.88 163.96 180 top
R6  150  [0603R]  138.3 159.89 90 top
R7  0  [0603R]  75.31 159.51 270 top
R8  0  [0603R]  79.5 159.51 90 top
R9  0  [0603R]  82.8 159.51 90 top
R10  0  [0603R]  85.6 159.51 90 top
R11  0  [0603R]  88.39 159.51 270 top
R12  100K  [0603R]  89.92 159.51 90 top
R13  3K3  [0603R]  105.66 159.51 270 top
R14  [N_A]  [0603R]  107.06 159.51 270 top
R15  120  [0603R]  138.3 156.84 90 top
R16  0  [0603R]  26.29 156.34 0 top
R17  0  [0603R]  80.31 149.91 270 top
R18  0  [0603R]  84.12 149.91 270 top
R19  0  [0603R]  76.96 149.86 90 top
R20  10K  [0603R]  86.11 149.86 90 top
R21  [N_A]  [0603R]  87.88 149.86 90 top
R22  33  [0402R]  66.55 148.84 180 top
R23  220K  [0603R]  92.58 148.08 270 top
R24  33  [0402R]  66.55 147.83 180 top
R25  10K  [0402R]  136.65 147.07 90 top
R26  33  [0402R]  66.55 146.81 180 top
R27  0  [0603R]  15.24 146.69 270 top
R28  47  [0603R]  16.76 146.69 270 top
R29  0  [0603R]  18.29 146.69 90 top
R30  0  [0603R]  21.08 146.69 90 top
R31  33  [0402R]  90.3 145.92 0 top
R32  220K  [0603R]  94.23 145.92 180 top
R33  0  [0603R]  66.67 144.78 90 top
R34  33  [0402R]  90.3 144.65 0 top
R35  33  [0402R]  90.3 143.38 0 top
R36  220K  [0603R]  94.23 143.38 180 top
R37  33  [0402R]  90.3 142.24 0 top
R38  220K  [0603R]  94.23 142.11 180 top
R39  33[N_A]  [0402R]  90.3 139.7 0 top
R40  220K  [0603R]  94.23 139.32 180 top
R41  33  [0402R]  66.55 139.06 180 top
R42  33  [0402R]  66.67 137.16 180 top
R43  33  [0402R]  90.3 136.78 0 top
R44  33  [0402R]  90.3 135.76 0 top
R45  33  [0603R]  124.71 129.29 90 top
R46  33  [0603R]  125.98 129.29 90 top
R47  33  [0603R]  127.25 129.29 90 top
R48  33  [0603R]  128.52 129.29 90 top
R49  33  [0603R]  130.18 129.29 90 top
R50  33  [0603R]  131.44 129.29 90 top
R51  33  [0402R]  64.52 126.11 270 top
R52  33  [0402R]  65.53 126.11 270 top
R53  33  [0402R]  66.55 126.11 270 top
R54  33  [0402R]  67.56 126.11 270 top
R55  33  [0402R]  68.58 126.11 270 top
R56  33  [0402R]  70.99 126.11 90 top
R57  33  [0402R]  72.39 126.11 90 top
R58  33  [0402R]  73.79 126.11 90 top
R59  33  [0402R]  75.18 126.11 270 top
R60  33  [0402R]  76.45 126.11 270 top
R61  33  [0402R]  79.63 126.11 270 top
R62  33  [0603R]  121.54 125.22 90 top
R63  33  [0402R]  64.52 122.81 270 top
R64  33  [0402R]  65.53 122.81 270 top
R65  33  [0402R]  66.55 122.81 270 top
R66  33  [0402R]  67.56 122.81 270 top
R67  33  [0402R]  68.58 122.81 270 top
R68  33  [0402R]  70.99 122.81 90 top
R69  33  [0402R]  72.39 122.81 90 top
R70  33  [0402R]  73.79 122.81 270 top
R71  33  [0402R]  75.18 122.81 270 top
R72  33  [0402R]  76.45 122.81 270 top
R73  0  [0603R]  136.02 122.81 0 top
R74  10K  [0603R]  121.54 120.78 90 top
R75  1K5  [0603R]  136.02 120.02 0 top
R76  2K2  [0603R]  136.02 118.62 0 top
R77  2K2  [0603R]  136.02 117.22 0 top
R78  240  [0603R]  152.53 116.59 180 top
R79  2K2  [0603R]  136.02 115.82 0 top
R80  22K  [0603R]  12.95 114.81 270 top
R81  2K2  [0603R]  127.89 114.43 270 top
R82  2K2  [0603R]  129.29 114.43 270 top
R83  4.87K  [0603R]  132.08 114.43 90 top
R84  47K  [0603R]  12.19 112.27 180 top
R85  10K  [0603R]  85.85 111.51 270 top
R86  22  [0603R]  125.09 111.12 0 top
R87  1M  [0603R]  28.57 110.74 180 top
R88  0  [0603R]  34.8 110.74 0 top
R89  50  [0603R]  136.78 110.74 0 top
R90  10K  [0603R]  74.8 110.62 180 top
R91  0  [0603R]  77.85 110.62 0 top
R92  10K  [0603R]  82.04 110.62 180 top
R93  22  [0603R]  125.09 109.86 0 top
R94  10K  [0603R]  19.05 109.6 90 top
R95  0  [0603R]  34.8 109.35 0 top
R96  330  [0603R]  8.13 109.22 0 top
R97  50  [0603R]  136.78 109.09 0 top
R98  12K[1%]  [0603R]  23.37 108.58 0 top
R99  22  [0603R]  125.09 108.58 0 top
R100  0  [0603R]  34.8 108.08 0 top
R101  22  [0603R]  125.09 107.31 0 top
R102  0  [0603R]  34.8 106.81 0 top
R103  820  [0603R]  23.37 106.55 180 top
R104  22  [0603R]  125.09 106.05 0 top
R105  22K  [0603R]  12.19 105.66 0 top
R106  0  [0603R]  34.8 105.54 0 top
R107  0  [0603R]  88.52 104.27 0 top
R108  47K  [0603R]  12.19 104.14 0 top
R109  0  [0603R]  34.8 104.14 0 top
R110  4K7  [0603R]  18.41 104.01 0 top
R111  [N_A]  [0603R]  124.59 103.89 90 top
R112  22  [0603R]  125.86 103.89 270 top
R113  [N_A]  [0603R]  128.02 103.89 90 top
R114  50  [0603R]  136.65 103.12 0 top
R115  0  [0603R]  34.8 102.87 0 top
R116  10K  [0603R]  88.52 102.74 0 top
R117  0  [0603R]  8.13 102.62 0 top
R118  330  [0603R]  12.19 102.62 0 top
R119  0  [0603R]  34.8 101.47 0 top
R120  50  [0603R]  136.65 101.47 0 top
R121  0  [0603R]  22.86 100.33 90 top
R122  3K3  [0603R]  24.13 100.33 90 top
R123  0  [0603R]  25.65 100.33 270 top
R124  0  [0603R]  27.18 100.33 270 top
R125  0  [0603R]  28.7 100.33 270 top
R126  33  [0603R]  29.97 100.33 270 top
R127  1K  [0603R]  20.7 99.44 90 top
R128  4K7  [0603R]  18.29 98.68 180 top
R129  10K  [0603R]  11.68 98.04 270 top
R130  0  [0603R]  13.21 98.04 90 top
R131  240  [0603R]  153.92 97.03 180 top
R132  0  [0603R]  12.19 91.44 180 top
R133  620  [0603R]  8.13 89.92 0 top
R134  47K  [0603R]  12.19 89.79 180 top
R135  330  [0603R]  12.19 87.88 0 top
R136  [N_A]  [0603R]  144.4 86.49 90 top
R137  [N_A]  [0603R]  145.8 86.49 90 top
R138  47K  [0603R]  8.13 81.28 0 top
R139  22K  [0603R]  12.19 81.28 180 top
R140  [N_A]  [0603R]  144.4 79.76 270 top
R141  [N_A]  [0603R]  145.8 79.76 90 top
R142  820  [0603R]  12.19 77.72 0 top
R143  [N_A]  [0603R]  145.03 73.41 180 top
R144  [N_A]  [0603R]  145.03 72.01 180 top
R145  10K  [0603R]  145.03 70.48 0 top
R146  10K  [0603R]  68.96 70.36 270 top
R147  0  [0603R]  70.36 70.36 270 top
R148  10K  [0603R]  145.29 65.53 0 top
R149  10K  [0603R]  145.29 62.48 0 top
R150  [N_A]  [0603R]  39.78 59.18 180 top
R151  5K6  [0402R]  37.49 58.55 270 top
R152  2K2  [0402R]  40.03 57.91 180 top
R153  0  [0603R]  39.78 56.64 0 top
R154  0  [0603R]  146.81 55.88 0 top
R155  10K[N_A]  [0603R]  138.18 53.85 180 top
R156  100K  [0603R]  31.88 53.21 90 top
R157  47K  [0603R]  138.18 52.32 0 top
R158  47K  [0603R]  138.18 50.8 0 top
R159  10K  [0402R]  35.71 48.59 0 top
R160  47K  [0603R]  138.18 46.74 0 top
R161  47K  [0603R]  138.18 45.21 0 top
R162  47K  [0603R]  138.18 43.69 0 top
R163  10K  [0603R]  138.18 40.13 0 top
R164  120  [0603R]  138.18 38.1 0 top
R165  0  [0603R]  48.39 37.34 270 top
R166  0  [0603R]  15.49 35.56 0 top
R167  [N_A]  [0603R]  60.58 35.31 90 top
R168  0  [0603R]  138.18 34.54 0 top
R169  0  [0603R]  15.49 34.04 0 top
R170  [N_A]  [0603R]  138.18 33.02 0 top
R171  1K5  [0603R]  15.49 32.51 0 top
R172  510  [0402R]  47.75 32 180 top
R173  100K  [0603R]  28.45 31.75 0 top
R174  0  [0603R]  138.18 31.5 0 top
R175  10K  [0402R]  47.75 30.99 180 top
R176  [N_A]  [0603R]  47.62 29.72 180 top
R177  2K2  [0603R]  112.39 29.21 0 top
R178  20  [0603R]  127.51 28.83 0 top
R179  20  [0603R]  127.51 27.43 0 top
R180  0  [0603R]  48.39 26.42 270 top
R181  47K[N_A]  [0402R]  49.78 26.67 90 top
R182  10K[N_A]  [0402R]  53.21 26.54 270 top
R183  [N_A]  [0603R]  148.97 152.15 0 bottom
R184  10K  [0603R]  31.24 26.42 90 top
R185  [N_A]  [0603R]  32.51 26.42 90 top
R186  4K7  [0603R]  37.85 26.42 90 top
R187  4K7  [0603R]  39.37 26.42 90 top
R188  10K  [0603R]  124.33 25.91 0 top
R189  0  [0603R]  127.51 25.91 180 top
R190  1K5  [0603R]  68.58 24.38 0 top
R191  1K5  [0603R]  71.63 24.38 180 top
R192  0  [0603R]  81.79 24.38 0 top
R193  0  [0603R]  119.63 23.24 270 top
R194  [N_A]  [0603R]  122.43 23.24 90 top
R195  0  [0603R]  123.83 23.24 90 top
R196  180  [0402R]  115.82 16.76 270 top
R197  1K  [0402R]  116.97 16.76 270 top
R198  10K  [0603R]  120.4 15.62 270 top
R199  10K  [0603R]  121.79 15.62 90 top
R200  1K  [0603R]  11.68 14.73 270 top
R201  100  [0603R]  14.73 14.73 270 top
R202  100  [0603R]  16.26 14.73 270 top
R203  0  [0603R]  17.78 14.73 90 top
R204  680  [0603R]  20.32 14.73 270 top
R205  [N_A]  [0603R]  22.35 14.73 270 top
R206  680  [0603R]  24.38 14.73 270 top
R207  [N_A]  [0603R]  26.42 14.73 270 top
R208  4K7  [0603R]  38.48 14.73 270 top
R209  2K7  [0603R]  39.88 14.73 90 top
R210  10K[N_A]  [0603R]  67.94 14.73 270 top
R211  10K[N_A]  [0603R]  70.74 14.73 270 top
R212  10K[N_A]  [0603R]  73.53 14.73 270 top
R213  10K[N_A]  [0603R]  76.33 14.73 270 top
R214  10K[N_A]  [0603R]  79.12 14.73 270 top
R215  0  [0603R]  102.62 14.73 270 top
R216  330  [0603R]  55.24 11.05 180 top
R217  220K  [0603R]  58.17 11.05 0 top
R218  100  [0603R]  62.61 11.05 0 top
R219  1K  [0402R]  106.55 8.89 90 top
R220  180  [0402R]  107.57 8.89 90 top
R221  0  [0603R]  115.95 8.89 90 top
R222  0  [0603R]  117.47 8.89 90 top
R223  [N_A]  [0603R]  142.11 3.68 270 top
R224  820  [0603R]  41.4 153.42 180 bottom
R225  0  [0603R]  65.79 152.27 0 bottom
R226  10K  [0402R]  34.92 152.02 270 bottom
R227  33  [0603R]  31.62 152.02 270 bottom
R228  33  [0603R]  29.84 152.02 90 bottom
R229  10K  [0603R]  148.97 150.62 0 bottom
R230  4K7  [0603R]  151.51 149.86 270 bottom
R231  [N_A]  [0603R]  148.97 149.22 180 bottom
R232  33  [0402R]  90.3 148.46 0 bottom
R233  33  [0402R]  90.3 147.19 0 bottom
R234  4K7  [0603R]  152.91 149.86 270 bottom
R235  [N_A]  [0603R]  148.97 146.18 180 bottom
R236  33  [0402R]  90.3 145.92 0 bottom
R237  33  [0603R]  31.62 145.8 90 bottom
R238  33  [0603R]  29.84 145.8 270 bottom
R239  33  [0402R]  90.3 144.65 0 bottom
R240  33  [0402R]  90.3 143.38 0 bottom
R241  33  [0603R]  41.27 142.88 180 bottom
R242  33  [0402R]  90.3 142.24 0 bottom
R243  33  [0603R]  115.44 141.35 0 bottom
R244  33  [0603R]  109.98 140.08 180 bottom
R245  33  [0402R]  90.3 139.7 180 bottom
R246  33  [0402R]  90.3 138.3 180 bottom
R247  33  [0603R]  109.98 137.29 0 bottom
R248  33  [0402R]  90.3 137.16 180 bottom
R249  10K  [0603R]  66.55 137.16 0 bottom
R250  33  [0402R]  90.3 136.02 180 bottom
R251  33  [0402R]  66.67 135.38 0 bottom
R252  33  [0603R]  109.98 134.49 0 bottom
R253  33  [0402R]  66.67 134.11 180 bottom
R254  33  [0402R]  64.01 134.11 0 bottom
R255  33  [0402R]  66.67 132.84 180 bottom
R256  33  [0402R]  64.01 132.84 180 bottom
R257  33  [0402R]  66.67 131.44 180 bottom
R258  33  [0402R]  64.01 131.44 180 bottom
R259  [N_A]  [0603R]  41.4 129.29 0 bottom
R260  0  [0603R]  115.32 128.65 180 bottom
R261  10K  [0603R]  109.98 128.02 180 bottom
R262  33  [0402R]  75.18 126.11 270 bottom
R263  33  [0402R]  73.79 126.11 270 bottom
R264  33  [0402R]  72.39 126.11 270 bottom
R265  33  [0402R]  70.99 126.11 90 bottom
R266  33  [0402R]  68.58 126.11 270 bottom
R267  33  [0402R]  86.23 125.73 270 bottom
R268  33  [0402R]  84.84 125.73 90 bottom
R269  33  [0402R]  83.44 125.73 90 bottom
R270  33  [0402R]  82.04 125.73 90 bottom
R271  33  [0402R]  80.64 125.73 90 bottom
R272  33  [0402R]  73.79 122.81 270 bottom
R273  33  [0402R]  72.39 122.81 270 bottom
R274  33  [0402R]  70.99 122.81 270 bottom
R275  0  [0603R]  109.98 122.43 0 bottom
R276  33  [0402R]  84.84 122.3 270 bottom
R277  33  [0402R]  83.57 122.3 90 bottom
R278  33  [0402R]  82.04 122.3 90 bottom
R279  33  [0402R]  80.64 122.3 90 bottom
R280  33  [0603R]  115.32 120.9 0 bottom
R281  0  [0603R]  109.98 120.9 0 bottom
R282  620  [0603R]  16 109.73 90 bottom
R283  0  [0603R]  8.13 100.58 0 bottom
R284  0  [0603R]  8.13 98.17 0 bottom
R285  10K  [0603R]  75.82 97.03 270 bottom
R286  22  [0603R]  8.13 86.23 0 bottom
R287  0  [0603R]  91.06 84.45 90 bottom
R288  22  [0603R]  8.13 83.82 0 bottom
R289  [N_A]  [0603R]  39.24 34.92 0 bottom
R290  0  [0603R]  52.96 34.67 180 bottom
R291  0  [0603R]  52.96 33.4 180 bottom
R292  100K  [0603R]  39.24 33.4 0 bottom
R293  10K  [0603R]  19.18 33.15 180 bottom
R294  100  [0603R]  21.46 32.51 90 bottom
R295  0  [0603R]  52.96 32.13 180 bottom
R296  36K  [0603R]  19.18 31.88 0 bottom
R297  100K  [0603R]  34.04 29.97 270 bottom
R298  [N_A]  [0603R]  153.29 152.27 0 bottom
R299  510  [0603R]  38.73 90.3 270 top
R300  680  [0603R]  109.22 54.48 180 top
R301  [N_A]  [0603R]  113.03 54.48 180 top
R302  [N_A]  [0603R]  38.61 94.74 270 top
RV1  3386P-103(10K)  [3386P]  34.54 8.13 180 top
SB1  Open  [SB_0603]  70.48 159.77 90 top
SB2  Open  [SB_0603]  64.14 159.64 90 top
SB3  Closed  [SB_0603]  89.66 148.08 270 top
SB4  Closed  [SB_0603]  91.19 148.08 270 top
SB5  Closed  [SB_0603]  108.97 159.38 270 top
SB6  Closed  [SB_0603]  94.23 144.65 180 top
SB7  Closed  [SB_0603]  90.3 140.84 180 top
SB8  Closed  [SB_0603]  94.23 140.84 180 top
SB9  Open  [SB_0603]  90.42 137.92 0 top
SB10  Closed  [SB_0603]  77.98 125.98 270 top
SB11  Closed  [SB_0603]  77.98 122.3 270 top
SB12  Closed  [SB_0603]  11.43 114.81 270 top
SB13  Open  [SB_0603]  14.73 114.81 90 top
SB14  Open  [SB_0603]  17.65 109.6 90 top
SB15  Closed  [SB_0603]  20.57 109.6 90 top
SB16  Closed  [SB_0603]  129.54 103.89 270 top
SB17  Closed  [SB_0603]  128.02 100.84 90 top
SB18  Closed  [SB_0603]  129.54 100.84 90 top
SB19  Open  [SB_0603]  34.42 59.56 0 top
SB20  Closed  [SB_0603]  121.92 15.24 180 bottom
SB21  Closed  [SB_0603]  128.4 15.24 0 bottom
SB22  Closed  [SB_0603]  46.86 146.05 0 bottom
SB23  Open  [SB_0603]  46.86 150.75 180 bottom
SB24  Closed  [SB_0603]  41.27 150.5 0 bottom
SB25  Open  [SB_0603]  83.95 149.48 90 bottom
SB26  Open  [SB_0603]  80.26 149.48 90 bottom
SB27  Open  [SB_0603]  76.96 149.48 90 bottom
SB28  Open  [SB_0603]  73.79 149.48 90 bottom
SB29  Closed  [SB_0603]  46.86 149.22 180 bottom
SB30  Open  [SB_0603]  41.27 148.84 0 bottom
SB31  Open  [SB_0603]  46.86 147.57 0 bottom
SB32  Closed  [SB_0603]  41.27 147.32 0 bottom
SB34  Open  [SB_0603]  41.27 145.8 0 bottom
SB35  Open  [SB_0603]  46.86 144.53 180 bottom
SB36  Open  [SB_0603]  41.27 144.27 0 bottom
SB37  Closed  [SB_0603]  46.86 143 180 bottom
SB38  Open  [SB_0603]  41.27 141.6 180 bottom
SB39  Open  [SB_0603]  46.86 140.84 180 bottom
SB40  Open  [SB_0603]  41.27 139.83 180 bottom
SB41  Closed  [SB_0603]  46.86 139.32 0 bottom
SB42  Open  [SB_0603]  109.98 138.56 180 bottom
SB43  Closed  [SB_0603]  41.27 138.3 180 bottom
SB44  Open  [SB_0603]  46.86 137.79 0 bottom
SB45  Closed  [SB_0603]  115.57 137.44 0 bottom
SB46  Open  [SB_0603]  109.98 135.76 180 bottom
SB47  Open  [SB_0603]  63.88 135.51 180 bottom
SB48  Open  [SB_0603]  115.32 133.22 180 bottom
SB49  Closed  [SB_0603]  115.32 131.7 180 bottom
SB50  Open  [SB_0603]  109.98 130.81 0 bottom
SB51  Open  [SB_0603]  41.4 130.68 0 bottom
SB52  Closed  [SB_0603]  115.32 130.18 180 bottom
SB53  Open  [SB_0603]  46.86 129.54 0 bottom
SB54  Closed  [SB_0603]  109.98 129.29 0 bottom
SB55  Closed  [SB_0603]  46.86 128.02 0 bottom
SB56  Open  [SB_0603]  115.32 127 180 bottom
SB57  Closed  [SB_0603]  115.32 125.48 180 bottom
SB58  Open  [SB_0603]  109.98 125.48 0 bottom
SB59  Open  [SB_0603]  46.74 124.21 180 bottom
SB60  Open  [SB_0603]  115.32 123.95 180 bottom
SB61  Closed  [SB_0603]  109.98 123.95 0 bottom
SB62  Open  [SB_0603]  115.32 122.43 0 bottom
SB63  Closed  [SB_0603]  109.98 119.63 0 bottom
SB64  Open  [SB_0603]  35.31 29.97 90 bottom
SW1  09.03290.01  [SW1_3TH_2R54_10X2R5]  48.26 167.64 0 top
T1  9012  [SOT-23]  18.29 101.35 0 top
T2  9013  [SOT-23]  12.7 83.82 270 top
T3  9013  [SOT-23]  19.05 32 180 top
T4  BSN20  [SOT-23]  149.22 154.69 270 bottom
T5  BSN20  [SOT-23]  153.16 154.81 270 bottom
T6  9013  [SOT-23]  10.16 110.74 270 bottom
T7  9013  [SOT-23]  12.7 103.12 0 bottom
TP1  1V8  [TP]  134.59 149.35 90 top
TP2  Ground  [TP]  48.26 163.83 0 top
TP3  Ground  [TP]  143.76 169.93 0 top
TP4  +3V3  [TP]  33.91 155.45 90 top
TP5  2V8  [TP]  128.09 155.65 90 top
TP6  VREF  [TP]  68.83 149.86 180 top
TP7  mco1  [TP]  154.05 119.38 0 top
TP8  mco1  [TP]  154.05 121.92 0 top
TP9  VDDA  [TP]  66.55 141.1 180 top
TP10  mco1  [TP]  154.05 124.33 0 top
TP11  mco1  [TP]  154.05 126.87 0 top
TP12  25MHz  [TP]  135.38 113.92 0 top
TP13  Ground  [TP]  33.93 92.08 0 top
TP14  5V  [TP]  12.7 65.02 0 top
TP15  mco1  [TP]  62.23 22.35 90 top
TP16  Ground  [TP]  89.41 4.32 0 top
U1  TFDU6300  [IR_VISHAY3]  136.27 169.93 0 top
U2  LD1117STR  [SOT-223]  132.84 155.96 180 top
U3  MT25QL512ABA8ESF-0SIT  [SOIC16W_1R27_10R3X10R33]  30.48 148.34 90 top
U4  STM32F7  [BGA216_0R8_13X13_SKT]  78.41 137.29 270 top
U5  ST3241EBPR  [SSOP28_0R65_10R2X7R8]  31.5 129.54 270 top
U6  DP83848CVV  [LQFP48_0R5_9X9]  128.02 121.79 0 top
U7  STMPS2151STR  [SOT23-5]  18.29 113.54 270 top
U8  USB3300-EZK  [QFN32_0R5_5X5]  28.45 106.05 0 top
U9  PC28F128M29EWLA  [FBGA64_1_11X13]  78.41 102.87 270 top
U10  ESDALC6V1W5  [SOT-353]  125.09 100.71 90 top
U11  STMPS2151STR  [SOT23-5]  10.67 94.49 0 top
U12  ESDALC6V1W5  [SOT-353]  145.29 83.06 0 top
U13  IS42S32800G-6BLI  [FBGA90_0R8_8X13]  91.06 78.74 270 top
U14  IS61WV102416BLL-10MLI  [BGA48_0R75_9X11]  66.04 78.23 270 top
U15  ESDALC6V1W5  [SOT-353]  145.29 76.2 180 top
U16  LD3985M33R  [SOT23-5]  24 71.5 90 top
U17  ST890CDR  [SOIC8_1R27_4R9X6]  35.59 53.21 0 top
U18  LD1086D2M33  [TO263-3]  49.15 53.85 180 top
U19  LD1117S18TR  [SOT-223]  109.86 43.31 180 top
U20  SN65HVD230  [SOIC8_1R27_4R9X6]  132.08 38.1 270 top
U21  STM32F103CBT6  [LQFP48_0R5_9X9]  35.69 33.66 90 top
U22  STM32L152CCT6  [LQFP48_0R5_9X9]  54.48 33.66 90 top
U23  WM8994ECS_R  [BGA72_0R5_4R5X4]  118.11 29.08 90 top
U24  -  [MP34DT01TR]  124.71 15.24 270 top
U25  -  [MP34DT01TR]  4.7 8.26 270 top
X1  25MHz(with socket)  [XTAL_SOCKET]  72.26 154.56 180 top
X2  NX3215SA-32.768KHZ-EXS00A-MU00525  [XTAL_2SM_3R2X1R5]  82.93 154.31 0 top
X3  SM7745HEX-24.0M[N_A]  [OSC_4SM_7X5]  141.6 147.07 0 top
X4  25MHz (with socket)  [XTAL_SOCKET]  140.72 125.22 90 top
X5  24MHz  [XTAL1]  26.04 115.32 180 top
X6  8MHz(12pF)  [XTAL_2SM_12R7X4R7]  35.05 22.23 180 top
Z1  SMAJ5.0A-TR  [SMA]  20.07 47.5 0 top

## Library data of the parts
B1 B2 = PB10
B3 = SW-JOY
BT1 = BAT_2SM_CR1220
C1 C2 C11 C15 C25 C27 C29 C33-C35 C37 C40-C46 C51 C52 C57 C60 C62 C68 C76 C77 C83 C84 C86 C89 C90 C96 C99 C101-C103 C119 C120 C134-C137 C140 C141 C143-C167 C169 C172 C174 C175 = 0603C: signal model: DEFAULT_CAPACITOR_100000pF_1_2
C3 C4 C36 C47 C48 C59 C106 C112 C142 = TAN-A: signal model: DEFAULT_CAPACITOR_4.7e+06pF_1_2
C5 C19 C56 C61 C70 C139 = TAN-A: signal model: DEFAULT_CAPACITOR_1e+07pF_1_2
C6-C10 C12-C14 C18 C24 C26 C28 C49 C50 C53 C55 C100 C104 C127 = 0603C
C16 = 0603C: signal model: DEFAULT_CAPACITOR_1000pF_1_2
C17 C91-C95 = 0603C: signal model: DEFAULT_CAPACITOR_10000pF_1_2
C20 C23 C80 C81 = 0603C: signal model: DEFAULT_CAPACITOR_20pF_1_2
C21 C22 = 0603C: signal model: DEFAULT_CAPACITOR_10pF_1_2
C30 C31 = 0603C: signal model: DEFAULT_CAPACITOR_22pF_1_2
C32 C138 = 1206C: signal model: DEFAULT_CAPACITOR_2.2e+06pF_2_1
C38 C39 = 0603C: signal model: DEFAULT_CAPACITOR_33pF_1_2
C54 = CAE_5R3X5R3_H5R4: signal model: DEFAULT_CAPACITOR_4.7e+07pF_2_1
C58 = C310M-6: signal model: DEFAULT_CAPACITOR_2.2e+08pF_1_2
C63 C65 C66 C72 C74 C85 C88 C98 = 0603C: signal model: DEFAULT_CAPACITOR_4.7e+06pF_1_2
C64 C67 C69 C87 = 0603C: signal model: DEFAULT_CAPACITOR_1e+06pF_1_2
C71 C73 C75 = 0603C: signal model: DEFAULT_CAPACITOR_2.2e+06pF_1_2
C78 C107-C110 C113-C118 C121-C126 C128-C133 C168 C170 C171 C173 C176 = 0402C: signal model: DEFAULT_CAPACITOR_100000pF_1_2
C79 = 0402C
C82 C105 C111 = TAN-A: signal model: DEFAULT_CAPACITOR_1e+06pF_1_2
C97 = 0603C: signal model: DEFAULT_CAPACITOR_30pF_1_2
CN1 = IDC34S
CN2 = SSM-104-L-DH
CN3 CN23 JP1-JP3 JP8 JP10 JP12 JP15 JP16 = SIP2
CN4 = CLM-120-02-L-D
CN5 CN6 = FTR-130-53-L-D-LC
CN7 CN22 = DB9_M
CN8 CN13 CN14 = MOLEX_47590001
CN9 = RJ45_J0011D01BNL
CN10 CN11 = FTR-120-53-L-D-LC
CN12 = FTSH-110-01-L-DV
CN15 = IDC20S
CN16 = MSD_PJS008_
CN17 = PWR_JACK_DC10
CN18 CN19 = HDR_2X3-1_2R54-6
CN20 = FTSH-125-01-F-DV
CN21 = USB-B
CN24 CN27 = COUPON
CN25 CN26 = PJ3028B
CN28 = CONN_DLR11H0
D1 D2 D7-D12 D15 D16 = SOD-323
D3 = BGA4_0R4_0R8X0R8
D4 = BGA4_0R4_1X1
D5 D6 = BGA11_0R5_1R57X2R07
D13 = TYCO_ZEN056V130A24LS
D14 T1-T7 = SOT-23
H1 H2 = HOLE_C9D4R5
JP4-JP7 JP9 JP11 JP14 JP17-JP24 = SIP3
JP13 = HDR_2X6_2R54
L1 L2 L4-L7 = 0603L
L3 = BNX001
LD1-LD11 = 0603D
LD12 = LED2_3528
R1 R28 = 0603R: signal model: DEFAULT_RESISTOR_47OHM_1_2
R2 = 0603R: signal model: DEFAULT_RESISTOR_5.1OHM_1_2
R3 R5 R7-R11 R14 R16-R19 R27 R29 R30 R33 R73 R87 R88 R91 R95 R100 R102 R106 R107 R109 R110 R115 R117 R119 R121 R123-R125 R128 R130 R132 R147 R150 R153 R154 R165 R166 R168 R169 R174 R180 R183 R189 R192 R193 R195 R203 R215 R221 R222 R225 R260 R275 R281 R287 R290 R291 R295 = 0603R: signal model: DEFAULT_RESISTOR_0.001OHM_1_2
R4 R20 R74 R85 R90 R92 R94 R116 R129 R145 R146 R148 R149 R155 R163 R184 R188 R198 R199 R210-R214 R229 R249 R261 R285 R293 = 0603R: signal model: DEFAULT_RESISTOR_10000OHM_1_2
R6 = 0603R: signal model: DEFAULT_RESISTOR_150OHM_1_2
R12 R156 R173 R292 R297 = 0603R: signal model: DEFAULT_RESISTOR_100000OHM_1_2
R13 R122 = 0603R: signal model: DEFAULT_RESISTOR_3300OHM_1_2
R15 R164 = 0603R: signal model: DEFAULT_RESISTOR_120OHM_1_2
R21 R105 R111 R113 R127 R136 R137 R139-R141 R143 R144 R170 R194 R259 = 0603R: signal model: 0603R_[n/a]
R22 R24 R26 R41-R43 = 0402R: signal model: DEFAULT_RESISTOR_33OHM_1_2
R23 R32 R36 R38 R40 R217 = 0603R: signal model: DEFAULT_RESISTOR_220000OHM_1_2
R25 R159 R175 R226 = 0402R: signal model: DEFAULT_RESISTOR_10000OHM_1_2
R31 R34 R35 R37 R39 R44 R51-R61 R63-R72 R232 R233 R236 R239 R240 R242 R245 R246 R248 R250 R251 R253-R258 R262-R274 R276-R279 = 0402R: signal model: 0402R_33
R45-R50 R62 R126 R227 R228 R237 R238 R241 R243 R244 R247 R252 R280 = 0603R: signal model: DEFAULT_RESISTOR_33OHM_1_2
R75 R171 R190 R191 = 0603R: signal model: DEFAULT_RESISTOR_1500OHM_1_2
R76 R77 R79 R81 R82 R177 = 0603R: signal model: DEFAULT_RESISTOR_2200OHM_1_2
R78 R131 = 0603R: signal model: DEFAULT_RESISTOR_240OHM_1_2
R80 R98 R167 R176 R185 R200 R223 R231 R235 R289 R298-R302 = 0603R
R83 = 0603R: signal model: DEFAULT_RESISTOR_4870OHM_1_2
R84 R108 R134 R138 R157 R158 R160-R162 = 0603R: signal model: DEFAULT_RESISTOR_47000OHM_1_2
R86 R93 R99 R101 R104 R112 R283 R284 R286 R288 = 0603R: signal model: DEFAULT_RESISTOR_22OHM_1_2
R89 R97 R114 R120 = 0603R: signal model: DEFAULT_RESISTOR_50OHM_1_2
R96 R118 R135 R216 = 0603R: signal model: DEFAULT_RESISTOR_330OHM_1_2
R103 R142 R224 = 0603R: signal model: DEFAULT_RESISTOR_820OHM_1_2
R133 R282 = 0603R: signal model: DEFAULT_RESISTOR_620OHM_1_2
R151 = 0402R: signal model: DEFAULT_RESISTOR_5600OHM_1_2
R152 = 0402R: signal model: DEFAULT_RESISTOR_2400OHM_1_2
R172 = 0402R: signal model: DEFAULT_RESISTOR_510OHM_1_2
R178 R179 = 0603R: signal model: DEFAULT_RESISTOR_20OHM_1_2
R181 R182 = 0402R
R186 R187 R208 R230 R234 = 0603R: signal model: DEFAULT_RESISTOR_4700OHM_1_2
R196 R220 = 0402R: signal model: DEFAULT_RESISTOR_180OHM_1_2
R197 R219 = 0402R: signal model: DEFAULT_RESISTOR_1000OHM_1_2
R201 R202 R218 R294 = 0603R: signal model: DEFAULT_RESISTOR_100OHM_1_2
R204-R206 = 0603R: signal model: DEFAULT_RESISTOR_680OHM_1_2
R207 = 0603R: signal model: DEFAULT_RESISTOR_510OHM_1_2
R209 = 0603R: signal model: DEFAULT_RESISTOR_2700OHM_1_2
R296 = 0603R: signal model: DEFAULT_RESISTOR_36000OHM_1_2
RV1 = 3386P
SB1-SB32 SB34-SB64 = SB_0603
SW1 = SW1_3TH_2R54_10X2R5
TP1-TP16 = TP
U1 = IR_VISHAY3
U2 U19 = SOT-223
U3 = SOIC16W_1R27_10R3X10R33
U4 = BGA216_0R8_13X13_SKT
U5 = SSOP28_0R65_10R2X7R8
U6 U21 U22 = LQFP48_0R5_9X9
U7 U11 U16 = SOT23-5
U8 = QFN32_0R5_5X5
U9 = FBGA64_1_11X13
U10 U12 U15 = SOT-353
U13 = FBGA90_0R8_8X13
U14 = BGA48_0R75_9X11
U17 U20 = SOIC8_1R27_4R9X6
U18 = TO263-3
U23 = BGA72_0R5_4R5X4
U24 U25 = MP34DT01TR
X1 X4 = XTAL_SOCKET
X2 = XTAL_2SM_3R2X1R5
X3 = OSC_4SM_7X5
X5 = XTAL1
X6 = XTAL_2SM_12R7X4R7
Z1 = SMA

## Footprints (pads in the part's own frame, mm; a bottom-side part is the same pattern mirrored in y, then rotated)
0402C
  rect 0.559x0.559 smd: 1(-0.508,0) 2(0.508,0)
0402R
  rect 0.559x0.559 smd: 1(-0.508,0) 2(0.508,0)
0603C
  rect 0.889x0.813 smd: 1(-0.762,0) 2(0.762,0)
0603D
  rect 0.889x0.813 smd: 1(-0.762,0) 2(0.762,0)
0603L
  rect 0.889x0.813 smd: 1(-0.762,0) 2(0.762,0)
0603R
  rect 0.787x0.813 smd: 1(-0.762,0) 2(0.762,0)
1206C
  rect 1.168x1.524 smd: 1(-1.473,0) 2(1.473,0)
3386P
  rect 1.168x1.168 hole 0.762: 1(-2.54,0)
  round 1.168 hole 0.762: 2(0,2.54) 3(2.54,0)
BAT_2SM_CR1220
  round 1.473 hole 1.473 unplated: (-3.75,0)
  round 1.194 hole 1.194 unplated: (3.75,0)
  rect 4.064x2.159 smd: 1(-7.95,0) 2(7.95,0)
BGA4_0R4_0R8X0R8
  round 0.203 smd: A1(-0.2,0.2) A2(0.2,0.2) B1(-0.2,-0.2) B2(0.2,-0.2)
BGA4_0R4_1X1
  round 0.203 smd: A1(-0.2,0.2) A2(0.2,0.2) B1(-0.2,-0.2) B2(0.2,-0.2)
BGA11_0R5_1R57X2R07
  round 0.249 smd: A2(0,0.75) A3(0.5,0.75) B1(-0.5,0.25) B2(0,0.25) B3(0.5,0.25) C1(-0.5,-0.25) C2(0,-0.25) C3(0.5,-0.25) D1(-0.5,-0.75) D2(0,-0.75) D3(0.5,-0.75)
BGA48_0R75_9X11
  round 0.356 smd: A1(-1.875,2.625) A2(-1.125,2.625) A3(-0.375,2.625) A4(0.375,2.625) A5(1.125,2.625) A6(1.875,2.625) B1(-1.875,1.875) B2(-1.125,1.875) B3(-0.375,1.875) B4(0.375,1.875) B5(1.125,1.875) B6(1.875,1.875) C1(-1.875,1.125) C2(-1.125,1.125) C3(-0.375,1.125) C4(0.375,1.125) C5(1.125,1.125) C6(1.875,1.125) D1(-1.875,0.375) D2(-1.125,0.375) D3(-0.375,0.375) D4(0.375,0.375) D5(1.125,0.375) D6(1.875,0.375) E1(-1.875,-0.375) E2(-1.125,-0.375) E3(-0.375,-0.375) E4(0.375,-0.375) E5(1.125,-0.375) E6(1.875,-0.375) F1(-1.875,-1.125) F2(-1.125,-1.125) F3(-0.375,-1.125) F4(0.375,-1.125) F5(1.125,-1.125) F6(1.875,-1.125) G1(-1.875,-1.875) G2(-1.125,-1.875) G3(-0.375,-1.875) G4(0.375,-1.875) G5(1.125,-1.875) G6(1.875,-1.875) H1(-1.875,-2.625) H2(-1.125,-2.625) H3(-0.375,-2.625) H4(0.375,-2.625) H5(1.125,-2.625) H6(1.875,-2.625)
BGA72_0R5_4R5X4
  round 0.249 smd: A1(-2,1.75) A2(-1.5,1.75) A3(-1,1.75) A4(-0.5,1.75) A5(0,1.75) A6(0.5,1.75) A7(1,1.75) A8(1.5,1.75) A9(2,1.75) B1(-2,1.25) B2(-1.5,1.25) B3(-1,1.25) B4(-0.5,1.25) B5(0,1.25) B6(0.5,1.25) B7(1,1.25) B8(1.5,1.25) B9(2,1.25) C1(-2,0.75) C2(-1.5,0.75) C3(-1,0.75) C4(-0.5,0.75) C5(0,0.75) C6(0.5,0.75) C7(1,0.75) C8(1.5,0.75) C9(2,0.75) D1(-2,0.25) D2(-1.5,0.25) D3(-1,0.25) D4(-0.5,0.25) D5(0,0.25) D6(0.5,0.25) D7(1,0.25) D8(1.5,0.25) D9(2,0.25) E1(-2,-0.25) E2(-1.5,-0.25) E3(-1,-0.25) E4(-0.5,-0.25) E5(0,-0.25) E6(0.5,-0.25) E7(1,-0.25) E8(1.5,-0.25) E9(2,-0.25) F1(-2,-0.75) F2(-1.5,-0.75) F3(-1,-0.75) F4(-0.5,-0.75) F5(0,-0.75) F6(0.5,-0.75) F7(1,-0.75) F8(1.5,-0.75) F9(2,-0.75) G1(-2,-1.25) G2(-1.5,-1.25) G3(-1,-1.25) G4(-0.5,-1.25) G5(0,-1.25) G6(0.5,-1.25) G7(1,-1.25) G8(1.5,-1.25) G9(2,-1.25) H1(-2,-1.75) H2(-1.5,-1.75) H3(-1,-1.75) H4(-0.5,-1.75) H5(0,-1.75) H6(0.5,-1.75) H7(1,-1.75) H8(1.5,-1.75) H9(2,-1.75)
BGA216_0R8_13X13_SKT
  round 1.702 hole 1.702 unplated: (-8.237,7.863) (-8.237,-7.863) (7.487,7.863) (7.487,-7.863)
  round 0.85 hole 0.85 unplated: (-8.237,-2.783) (7.487,5.323)
  round 0.406 smd: A1(-5.6,5.6) A2(-4.8,5.6) A3(-4,5.6) A4(-3.2,5.6) A5(-2.4,5.6) A6(-1.6,5.6) A7(-0.8,5.6) A8(0,5.6) A9(0.8,5.6) A10(1.6,5.6) A11(2.4,5.6) A12(3.2,5.6) A13(4,5.6) A14(4.8,5.6) A15(5.6,5.6) B1(-5.6,4.8) B2(-4.8,4.8) B3(-4,4.8) B4(-3.2,4.8) B5(-2.4,4.8) B6(-1.6,4.8) B7(-0.8,4.8) B8(0,4.8) B9(0.8,4.8) B10(1.6,4.8) B11(2.4,4.8) B12(3.2,4.8) B13(4,4.8) B14(4.8,4.8) B15(5.6,4.8) C1(-5.6,4) C2(-4.8,4) C3(-4,4) C4(-3.2,4) C5(-2.4,4) C6(-1.6,4) C7(-0.8,4) C8(0,4) C9(0.8,4) C10(1.6,4) C11(2.4,4) C12(3.2,4) C13(4,4) C14(4.8,4) C15(5.6,4) D1(-5.6,3.2) D2(-4.8,3.2) D3(-4,3.2) D4(-3.2,3.2) D5(-2.4,3.2) D6(-1.6,3.2) D7(-0.8,3.2) D8(0,3.2) D9(0.8,3.2) D10(1.6,3.2) D11(2.4,3.2) D12(3.2,3.2) D13(4,3.2) D14(4.8,3.2) D15(5.6,3.2) E1(-5.6,2.4) E2(-4.8,2.4) E3(-4,2.4) E4(-3.2,2.4) E5(-2.4,2.4) E6(-1.6,2.4) E7(-0.8,2.4) E8(0,2.4) E9(0.8,2.4) E10(1.6,2.4) E11(2.4,2.4) E12(3.2,2.4) E13(4,2.4) E14(4.8,2.4) E15(5.6,2.4) F1(-5.6,1.6) F2(-4.8,1.6) F3(-4,1.6) F4(-3.2,1.6) F5(-2.4,1.6) F6(-1.6,1.6) F7(-0.8,1.6) F8(0,1.6) F9(0.8,1.6) F10(1.6,1.6) F11(2.4,1.6) F12(3.2,1.6) F13(4,1.6) F14(4.8,1.6) F15(5.6,1.6) G1(-5.6,0.8) G2(-4.8,0.8) G3(-4,0.8) G4(-3.2,0.8) G5(-2.4,0.8) G6(-1.6,0.8) G10(1.6,0.8) G11(2.4,0.8) G12(3.2,0.8) G13(4,0.8) G14(4.8,0.8) G15(5.6,0.8) H1(-5.6,0) H2(-4.8,0) H3(-4,0) H4(-3.2,0) H5(-2.4,0) H6(-1.6,0) H10(1.6,0) H11(2.4,0) H12(3.2,0) H13(4,0) H14(4.8,0) H15(5.6,0) J1(-5.6,-0.8) J2(-4.8,-0.8) J3(-4,-0.8) J4(-3.2,-0.8) J5(-2.4,-0.8) J6(-1.6,-0.8) J10(1.6,-0.8) J11(2.4,-0.8) J12(3.2,-0.8) J13(4,-0.8) J14(4.8,-0.8) J15(5.6,-0.8) K1(-5.6,-1.6) K2(-4.8,-1.6) K3(-4,-1.6) K4(-3.2,-1.6) K5(-2.4,-1.6) K6(-1.6,-1.6) K7(-0.8,-1.6) K8(0,-1.6) K9(0.8,-1.6) K10(1.6,-1.6) K11(2.4,-1.6) K12(3.2,-1.6) K13(4,-1.6) K14(4.8,-1.6) K15(5.6,-1.6) L1(-5.6,-2.4) L2(-4.8,-2.4) L3(-4,-2.4) L4(-3.2,-2.4) L5(-2.4,-2.4) L6(-1.6,-2.4) L7(-0.8,-2.4) L8(0,-2.4) L9(0.8,-2.4) L10(1.6,-2.4) L11(2.4,-2.4) L12(3.2,-2.4) L13(4,-2.4) L14(4.8,-2.4) L15(5.6,-2.4) M1(-5.6,-3.2) M2(-4.8,-3.2) M3(-4,-3.2) M4(-3.2,-3.2) M5(-2.4,-3.2) M6(-1.6,-3.2) M7(-0.8,-3.2) M8(0,-3.2) M9(0.8,-3.2) M10(1.6,-3.2) M11(2.4,-3.2) M12(3.2,-3.2) M13(4,-3.2) M14(4.8,-3.2) M15(5.6,-3.2) N1(-5.6,-4) N2(-4.8,-4) N3(-4,-4) N4(-3.2,-4) N5(-2.4,-4) N6(-1.6,-4) N7(-0.8,-4) N8(0,-4) N9(0.8,-4) N10(1.6,-4) N11(2.4,-4) N12(3.2,-4) N13(4,-4) N14(4.8,-4) N15(5.6,-4) P1(-5.6,-4.8) P2(-4.8,-4.8) P3(-4,-4.8) P4(-3.2,-4.8) P5(-2.4,-4.8) P6(-1.6,-4.8) P7(-0.8,-4.8) P8(0,-4.8) P9(0.8,-4.8) P10(1.6,-4.8) P11(2.4,-4.8) P12(3.2,-4.8) P13(4,-4.8) P14(4.8,-4.8) P15(5.6,-4.8) R1(-5.6,-5.6) R2(-4.8,-5.6) R3(-4,-5.6) R4(-3.2,-5.6) R5(-2.4,-5.6) R6(-1.6,-5.6) R7(-0.8,-5.6) R8(0,-5.6) R9(0.8,-5.6) R10(1.6,-5.6) R11(2.4,-5.6) R12(3.2,-5.6) R13(4,-5.6) R14(4.8,-5.6) R15(5.6,-5.6)
BNX001
  round 1.981 hole 1.219: 1(2.5,2.5) 2(-2.5,2.5) 3(2.5,-2.5) 4(0,0) 5(5,0) 6(-2.5,-2.5)
C310M-6
  rect 5.08x3.048 smd: 1(3.175,0) 2(-3.175,0)
CAE_5R3X5R3_H5R4
  rect 2.718x1.168 smd: 1(-2.05,0) 2(2.05,0)
